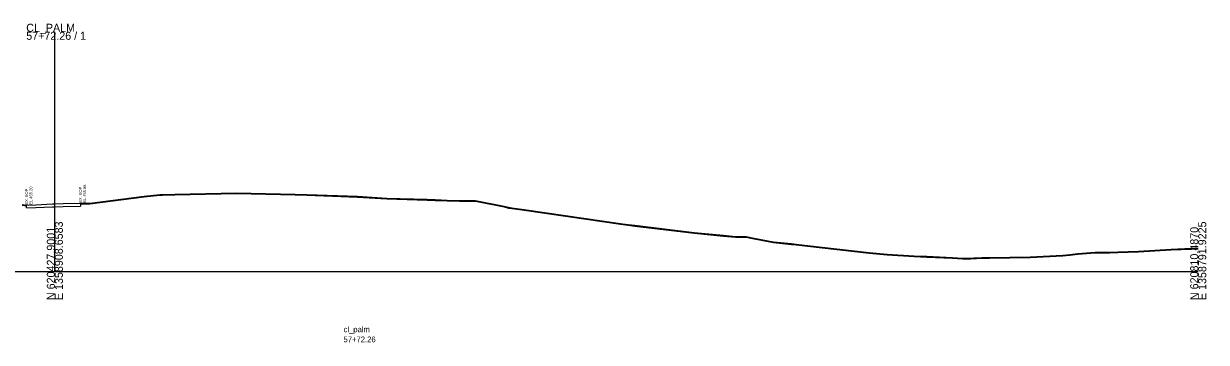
# Model space of a CAD drawing. Extents: x -26 to 803, y -27 to 3586.
# Drawn here: x 389.1 to 802.8, y 2975.2 to 3086.7 of the extents above; entities that cross this region are included whole.
import ezdxf

# ---------------------------------------------------------------- set-up
doc = ezdxf.new("R2010")
doc.units = 0
for name, color, linetype in [('DESIGN - SHEET - Light Grid', 7, 'Continuous'), ('DESIGN - TYPICAL - Warning Text', 7, 'Continuous'), ('SURVEY - GROUND - Bottom of Topsoil Layer', 7, 'Continuous'), ('SURVEY - GROUND - Existing Pavement Layer', 7, 'Continuous'), ('SURVEY - GROUND - Existing Pavement Text', 7, 'Continuous'), ('SURVEY - GROUND - Top of Ground', 7, 'Continuous')]:
    doc.layers.add(name, color=color, linetype=linetype)

msp = doc.modelspace()

# ---------------------------------------------------------------- linework, layer by layer
at = {"layer": 'DESIGN - SHEET - Light Grid'}
for p, q in [((400, 3000), (400, 3083.82)), ((0, 3000), (400, 3000)), ((400, 3000), (800, 3000))]:
    msp.add_line(p, q, dxfattribs=at)
at = {"layer": 'SURVEY - GROUND - Bottom of Topsoil Layer'}
for p, q in [((412.25, 3023.6), (431.26, 3026.07)), ((431.26, 3026.07), (436.69, 3026.72)), ((436.69, 3026.72), (437.63, 3026.68)), ((437.63, 3026.68), (442, 3026.82)), ((442, 3026.82), (463.6, 3027.25)), ((463.6, 3027.25), (484.08, 3026.84)), ((484.08, 3026.84), (488.27, 3026.67)), ((488.27, 3026.67), (505.83, 3026.04)), ((505.83, 3026.04), (516.09, 3025.38)), ((516.09, 3025.38), (530.25, 3024.98)), ((530.25, 3024.98), (532.44, 3024.89)), ((532.44, 3024.89), (533.02, 3024.87)), ((533.02, 3024.87), (537.29, 3024.72)), ((537.29, 3024.72), (541.61, 3024.54)), ((541.61, 3024.54), (547.13, 3024.6)), ((547.13, 3024.6), (557.14, 3022.55)), ((388.58, 3023.15), (390.12, 3022.95)), ((390.12, 3022.95), (390.12, 3023.2)), ((408.94, 3023.63), (408.94, 3023.88)), ((408.94, 3023.63), (412.25, 3023.6)), ((557.14, 3022.55), (558.75, 3022.19)), ((558.75, 3022.19), (559.86, 3022.05)), ((559.86, 3022.05), (563.39, 3021.55)), ((563.39, 3021.55), (572.25, 3020.27)), ((572.25, 3020.27), (597.88, 3016.56)), ((597.88, 3016.56), (599.65, 3016.28)), ((599.65, 3016.28), (600.62, 3016.16)), ((600.62, 3016.16), (602.9, 3015.9)), ((602.9, 3015.9), (623.61, 3013.35)), ((623.61, 3013.35), (633.91, 3012.39)), ((633.91, 3012.39), (638.14, 3011.96)), ((638.14, 3011.96), (639.5, 3012)), ((639.5, 3012), (641.9, 3012.02)), ((641.9, 3012.02), (644.63, 3011.39)), ((644.63, 3011.39), (651.42, 3010.14)), ((651.42, 3010.14), (657.77, 3009.48)), ((657.77, 3009.48), (659.34, 3009.29)), ((659.34, 3009.29), (663.28, 3008.86)), ((663.28, 3008.86), (684.83, 3006.42)), ((684.83, 3006.42), (691.13, 3005.84)), ((691.13, 3005.84), (700.66, 3005.26)), ((700.66, 3005.26), (705, 3005.06)), ((705, 3005.06), (713.98, 3004.61)), ((713.98, 3004.61), (717.56, 3004.41)), ((717.56, 3004.41), (718.06, 3004.41)), ((718.06, 3004.41), (718.57, 3004.36)), ((718.57, 3004.36), (724.35, 3004.61)), ((724.35, 3004.61), (725.26, 3004.6)), ((725.26, 3004.6), (726.98, 3004.65)), ((726.98, 3004.65), (741.22, 3004.9)), ((741.22, 3004.9), (752.6, 3005.48)), ((752.6, 3005.48), (755.08, 3005.69)), ((755.08, 3005.69), (757.92, 3006.04)), ((757.92, 3006.04), (763.91, 3006.53)), ((763.91, 3006.53), (766.39, 3006.49)), ((766.39, 3006.49), (769.09, 3006.5)), ((769.09, 3006.5), (771.91, 3006.61)), ((771.91, 3006.61), (779.13, 3006.87)), ((779.13, 3006.87), (790.48, 3007.55)), ((790.48, 3007.55), (797.63, 3007.86)), ((797.63, 3007.86), (800, 3007.94))]:
    msp.add_line(p, q, dxfattribs=at)
at = {"layer": 'SURVEY - GROUND - Existing Pavement Layer'}
for p, q in [((390.12, 3022.2), (390.12, 3023.2)), ((390.12, 3022.2), (393.37, 3022.35)), ((393.37, 3022.35), (399.17, 3022.64)), ((399.17, 3022.64), (400, 3022.66)), ((400, 3022.66), (402.97, 3022.73)), ((402.97, 3022.73), (408.94, 3022.88)), ((408.94, 3023.88), (408.94, 3022.88))]:
    msp.add_line(p, q, dxfattribs=at)
at = {"layer": 'SURVEY - GROUND - Top of Ground'}
msp.add_lwpolyline([(388.58, 3023.4), (390.12, 3023.2), (393.37, 3023.35), (399.17, 3023.64), (400, 3023.66), (402.97, 3023.73), (408.94, 3023.88), (412.25, 3023.85), (431.26, 3026.32), (436.69, 3026.97), (437.63, 3026.93), (442, 3027.07), (463.6, 3027.5), (484.08, 3027.09), (488.27, 3026.92), (505.83, 3026.29), (516.09, 3025.63), (530.25, 3025.23), (532.44, 3025.14), (533.02, 3025.12), (537.29, 3024.97), (541.61, 3024.79), (547.13, 3024.85), (557.14, 3022.8), (558.75, 3022.44), (559.86, 3022.3), (563.39, 3021.8), (572.25, 3020.52), (597.88, 3016.81), (599.65, 3016.53), (600.62, 3016.41), (602.9, 3016.15), (623.61, 3013.6), (633.91, 3012.64), (638.14, 3012.21), (639.5, 3012.25), (641.9, 3012.27), (644.63, 3011.64), (651.42, 3010.39), (657.77, 3009.73), (659.34, 3009.54), (663.28, 3009.11), (684.83, 3006.67), (691.13, 3006.09), (700.66, 3005.51), (705, 3005.31), (713.98, 3004.86), (717.56, 3004.66), (718.06, 3004.66), (718.57, 3004.61), (724.35, 3004.86), (725.26, 3004.85), (726.98, 3004.9), (741.22, 3005.15), (752.6, 3005.73), (755.08, 3005.94), (757.92, 3006.29), (763.91, 3006.78), (766.39, 3006.74), (769.09, 3006.75), (771.91, 3006.86), (779.13, 3007.12), (790.48, 3007.8), (797.63, 3008.11), (800, 3008.19)], dxfattribs=at)

# ---------------------------------------------------------------- texts
at = {"layer": 'DESIGN - SHEET - Light Grid'}
for s, p in [('CL_PALM', (390, 3083.82)), ('57+72.26 / 1', (390, 3081.02))]:
    msp.add_text(s, height=2.8, dxfattribs=at).set_placement(p)
for s, p in [('E 1358908.6583', (402.8, 2990)), ('E 1358791.9225', (802.8, 2990)), ('N 620427.9001', (400, 2990)), ('N 620810.4870', (800, 2990))]:
    msp.add_text(s, height=2.8, rotation=90, dxfattribs=at).set_placement(p)
at = {"layer": 'DESIGN - TYPICAL - Warning Text'}
for s, p in [('cl_palm', (501, 2978.75)), ('57+72.26', (501, 2975.25))]:
    msp.add_text(s, height=2, dxfattribs=at).set_placement(p)
at = {"layer": 'SURVEY - GROUND - Existing Pavement Text'}
for s, p in [('EX. EOP', (390.62, 3023.4)), ('EL.455.20', (392.12, 3023.4)), ('EX. EOP', (409.44, 3024.08)), ('EL.455.88', (410.94, 3024.08))]:
    msp.add_text(s, height=1, rotation=90, dxfattribs=at).set_placement(p)

doc.saveas('drawing.dxf')
